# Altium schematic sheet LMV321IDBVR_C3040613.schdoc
size 127 x 101 mm
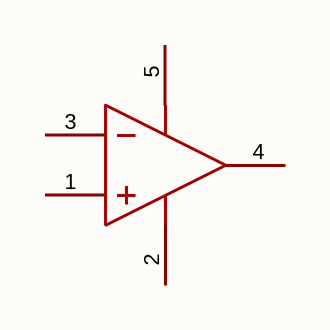
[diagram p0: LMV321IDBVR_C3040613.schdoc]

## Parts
U?  lmv321idbvr  [SOT-23-5_L3.0-W1.5-P0.95-LS2.8-BL]  (value not drawn)

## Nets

Not connected (* = marked no-connect by the designer): U? 1(+IN) 2(V-) 3(-IN) 4(OUT) 5(V+)

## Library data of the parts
U? = lmv321idbvr: 放大器数:1;轨到轨:轨到轨输入,轨到轨输出;增益带宽积(GBW):1MHz;输入失调电压(Vos):5mV;压摆率(SR):600V/ms;输入偏置电流(Ib):10pA;; Manufacturer: TECH PUBLIC(台舟); Symbol: LMV321IDBVR_C3040613; AddInBom: yes; ModelId: 424d41c645fb4cc2a3598f66fad27964; ModelTransform: 118.11,110.236,0,0,0,0,0,0,0; Number of Channels: 1; Maximum Power Supply Range (Vdd-Vss): 5.5V; Gain Bandwidth Product: 1MHz; Vos - Input Offset Voltage: 5mV; Input Offset Voltage Drift(Vos TC): 2uV/℃; Ib - Input Bias Current: 10pA; Input Voltage Noise Density: 20nV/√Hz@10kHz; Common Mode Rejection Ratio(CMRR): 65dB; Quiescent Current: 40uA; Output Current: 20mA; Single supply: 2.2V~5.5V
